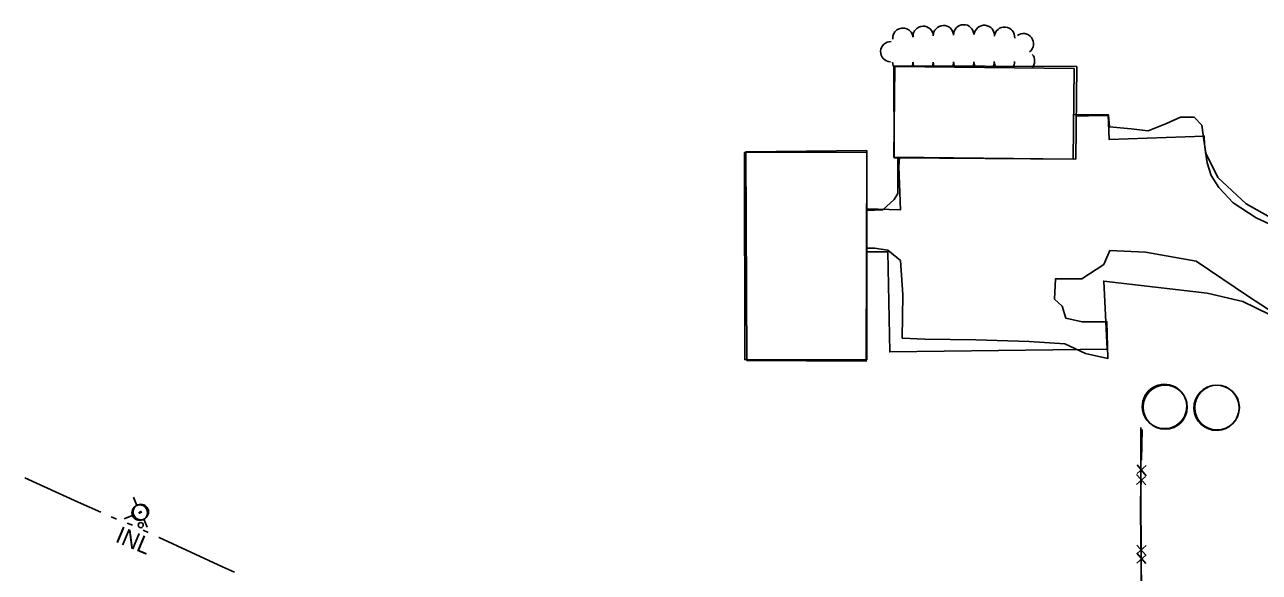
# Model space of a CAD drawing. Extents: x 588843 to 2552415, y 180129 to 269402.
# Drawn here: x 595443.9 to 595880.6, y 184935.1 to 185128.9 of the extents above; entities that cross this region are included whole.
import ezdxf

# ---------------------------------------------------------------- set-up
doc = ezdxf.new("R2010")
doc.units = 0
for name, color, linetype in [('Default', 7, 'Continuous'), ('E_BLD', 7, 'Continuous'), ('E_DRN', 7, 'Continuous'), ('E_DRN_Text', 7, 'Continuous'), ('E_DWY', 7, 'Continuous'), ('E_FEN_P', 7, 'Continuous'), ('E_LAND_TreeLine_P', 7, 'Continuous'), ('E_UTL_WHydrant', 7, 'Continuous'), ('E_WTR_P', 7, 'Continuous'), ('Level 12', 7, 'Continuous'), ('Level 15', 7, 'Continuous'), ('Level 17', 7, 'Continuous')]:
    doc.layers.add(name, color=color, linetype=linetype)

# ---------------------------------------------------------------- blocks, each defined once
blk = doc.blocks.new('HYD')
at = {"layer": 'Default'}
for p, q in [((-3.84, 3.84), (-8.32, 8.32)), ((3.84, 3.84), (8.32, 8.32))]:
    blk.add_line(p, q, dxfattribs=at)
for radius in [5.48, 0.42]:
    blk.add_circle((0, 0), radius, dxfattribs=at)
blk = doc.blocks.new('INLT_55')
at = {"layer": 'E_DRN_Text'}
blk.add_text('INL', height=12, dxfattribs=at).set_placement((-11.03, -6))
blk = doc.blocks.new('HYD_3')
at = {"layer": 'E_UTL_WHydrant'}
for p, q in [((-12.6, 12.6), (-27.3, 27.3)), ((12.6, 12.6), (27.3, 27.3))]:
    blk.add_line(p, q, dxfattribs=at)
for radius in [18, 1.38]:
    blk.add_circle((0, 0), radius, dxfattribs=at)

msp = doc.modelspace()

# ---------------------------------------------------------------- linework, layer by layer
at = {"layer": 'E_BLD'}
for points in [[(595751.67, 185114.13), (595815.07, 185113.42), (595814.71, 185081.28), (595751.31, 185081.99)], [(595698.62, 185010.29), (595698.52, 185083.66), (595741.71, 185083.71), (595741.81, 185010.35)]]:
    msp.add_lwpolyline(points, close=True, dxfattribs=at)
for centre, radius in [((595847.25, 184993.55), 7.81), ((595865.62, 184993.38), 7.91)]:
    msp.add_circle(centre, radius, dxfattribs=at)
at = {"layer": 'E_DRN'}
msp.add_circle((595484.97, 184951.76), 0.914, dxfattribs=at)
at = {"layer": 'E_DWY'}
for points in [[(595921.45, 185070.98), (595922.54, 185057.9), (595920.89, 185057.13), (595904.48, 185054.95), (595894.66, 185055.03), (595887.57, 185056.81), (595879.47, 185060.51), (595871.33, 185065.86), (595866.28, 185071.28), (595863.57, 185075.52), (595862.16, 185080.02), (595861.57, 185083.78), (595861.12, 185086.57), (595861.1, 185089.44), (595827.44, 185088.29), (595827.11, 185097), (595814.89, 185097.06)], [(595753.3, 185081.97), (595753.11, 185078.52), (595753.7, 185063.38), (595741.74, 185063.76)], [(595741.76, 185048.54), (595749.13, 185048.55), (595749.87, 185013.06), (595826.76, 185014.01), (595825.52, 185038.16), (595862.08, 185033.88), (595874.7, 185030.97), (595884.18, 185026.37)]]:
    msp.add_lwpolyline(points, dxfattribs=at)
at = {"layer": 'E_FEN_P'}
for p, q in [((595837.32, 184973.11), (595840.52, 184969.27)), ((595840.6, 184972.87), (595837.33, 184970.1)), ((595837.21, 184944.73), (595840.53, 184940.99)), ((595840.49, 184944.59), (595837.3, 184941.72))]:
    msp.add_line(p, q, dxfattribs=at)
for points in [[(595839.1, 184985.56), (595838.87, 184974.74)], [(595838.73, 184968.04), (595838.56, 184960.17), (595838.59, 184957.23)], [(595838.59, 184957.23), (595838.7, 184946.41)], [(595838.77, 184939.71), (595838.88, 184928.89)]]:
    msp.add_lwpolyline(points, dxfattribs=at)
at = {"layer": 'E_LAND_TreeLine_P'}
for centre, start, end in [((595768.85, 185125.03), 2.0835, 182.0835), ((595776.03, 185125.3), 2.0835, 182.0835), ((595783.3, 185125.09), 355.0479, 175.0479), ((595754.51, 185124.12), 6.3202, 186.3202), ((595761.67, 185124.77), 2.0835, 182.0835), ((595790.46, 185124.47), 355.0479, 175.0479), ((595797.15, 185122.15), 307.1367, 127.1367), ((595750.2, 185119.33), 87.9985, 267.9985), ((595754.47, 185115.65), 179.7216, 218.5865), ((595754.47, 185115.65), 333.8296, 359.7216), ((595761.66, 185115.61), 179.7216, 205.6947), ((595761.66, 185115.61), 333.0262, 359.7216), ((595768.84, 185115.66), 180.4268, 208.0456), ((595768.84, 185115.66), 330.6753, 0.4268), ((595776.03, 185115.72), 180.4268, 210.5065), ((595776.03, 185115.72), 328.2143, 0.4268), ((595783.22, 185115.77), 180.4268, 213.0331), ((595783.22, 185115.77), 325.6877, 0.4268), ((595790.41, 185115.82), 180.4268, 215.6363), ((595790.41, 185115.82), 323.0845, 0.4268), ((595797.52, 185116.09), 315.9211, 39.863), ((595797.52, 185116.09), 219.863, 222.7997)]:
    msp.add_arc(centre, 3.59, start, end, dxfattribs=at)
at = {"layer": 'E_WTR_P'}
for points in [[(595443.93, 184968.46), (595462.87, 184959.88), (595470.81, 184956.34)], [(595474.53, 184954.69), (595475.91, 184954.08), (595476.39, 184953.89)], [(595480.2, 184952.45), (595482.03, 184951.75), (595482.09, 184951.72)], [(595485.78, 184950.01), (595487.63, 184949.15)], [(595491.32, 184947.44), (595491.47, 184947.36), (595513.9, 184936.99), (595518.08, 184935.07)]]:
    msp.add_lwpolyline(points, dxfattribs=at)
at = {"layer": 'Level 12'}
for points in [[(595815.68, 185081.27), (595751.47, 185081.76), (595751.36, 185114.34), (595815.99, 185114.04), (595815.68, 185081.27)], [(595741.76, 185084.3), (595741.48, 185009.76), (595699.37, 185010.03), (595698.99, 185083.9), (595741.76, 185084.3)]]:
    msp.add_lwpolyline(points, dxfattribs=at)
for centre, radius, start, end in [((595847.02, 184993.78), 7.85, 1.577, 181.5846), ((595865.42, 184993.29), 8.01, 91.7572, 271.7572), ((595865.42, 184993.29), 8.01, 271.7572, 91.7572), ((595847.02, 184993.77), 7.85, 181.577, 1.5846)]:
    msp.add_arc(centre, radius, start, end, dxfattribs=at)
at = {"layer": 'Level 15'}
for p, q in [((595840.39, 184966.01), (595837.14, 184969.72)), ((595837.15, 184966.18), (595840.31, 184968.98)), ((595840.46, 184938.15), (595837.21, 184941.86)), ((595837.22, 184938.32), (595840.38, 184941.12))]:
    msp.add_line(p, q, dxfattribs=at)
for points in [[(595838.77, 184917.13), (595838.6, 184986.37)], [(595838.61, 184982.75), (595838.6, 184986.37)], [(595838.64, 184971.43), (595838.61, 184982.75)], [(595838.68, 184954.89), (595838.65, 184964.85)], [(595838.7, 184943.57), (595838.68, 184954.89)], [(595838.75, 184927.03), (595838.72, 184936.99)]]:
    msp.add_lwpolyline(points, dxfattribs=at)
at = {"layer": 'Level 17'}
for points in [[(595815.82, 185096.45), (595820.19, 185096.57), (595827.26, 185096.77), (595827.54, 185092.68)], [(595922.25, 185070.84), (595921.87, 185062.56), (595915.89, 185057.46), (595907.27, 185056.18), (595896.47, 185056.13), (595888.3, 185058.49), (595875.87, 185065.53), (595865.91, 185074.77), (595861.66, 185083.38), (595861.1, 185087.25), (595860.22, 185093.37), (595857.48, 185096.1), (595852.68, 185096.19), (595847.68, 185093.88), (595841.28, 185091.36), (595835.27, 185091.99), (595827.54, 185092.68)], [(595741.68, 185063.17), (595747.43, 185063.36), (595751.41, 185067.06), (595752.73, 185069.18), (595752.66, 185081.75)], [(595827.72, 185048.91), (595825.56, 185043.96), (595817.77, 185038.9), (595808.42, 185038.89), (595808.16, 185031.71), (595810.79, 185029.26), (595812.16, 185024.97), (595817.85, 185023.69), (595826.68, 185023.76), (595826.99, 185010.76), (595819.06, 185012.5), (595811.79, 185015.99), (595799.13, 185016.77), (595780.3, 185017.37), (595762.23, 185017.62), (595754.29, 185017.95), (595754.51, 185033.26), (595753.66, 185045.37), (595749.15, 185049.08), (595744.47, 185049.81), (595741.63, 185049.75)], [(595827.72, 185048.91), (595840.32, 185048.35), (595858.2, 185045.2), (595876.79, 185032.69), (595894.91, 185020.89), (595908.1, 185008.69), (595916.55, 184996.93), (595921.62, 184980.35), (595924.34, 184960.15), (595926.11, 184943.13), (595927.19, 184922.35), (595927.91, 184903.95), (595927.89, 184883.35), (595926.19, 184867.84), (595926.07, 184865.69)]]:
    msp.add_lwpolyline(points, dxfattribs=at)

# ---------------------------------------------------------------- block references
at = {"layer": 'E_DRN_Text', "xscale": 0.4999999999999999, "yscale": 0.5, "rotation": -22.87015224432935}
msp.add_blockref('INLT_55', (595481.86, 184946.63), dxfattribs=at)
at = {"layer": 'E_UTL_WHydrant'}
for name, p, xscale, yscale, rotation in [('HYD_3', (595484.6, 184956.17), 0.1524003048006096, 0.15240030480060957, 67.12813611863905), ('HYD', (595485, 184956.44), 0.5, 0.5000000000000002, 157.32170144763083)]:
    msp.add_blockref(name, p, dxfattribs=dict(at, xscale=xscale, yscale=yscale, rotation=rotation))

doc.saveas('drawing.dxf')
